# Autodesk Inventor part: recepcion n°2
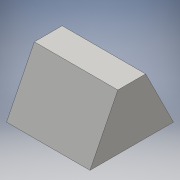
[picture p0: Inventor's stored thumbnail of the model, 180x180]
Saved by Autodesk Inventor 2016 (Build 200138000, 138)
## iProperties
Created: 2016-06
Part Number: recepcion n°2
Material: Genérico
Document SubType Name: Modeling
Designer: adm
Density: 1 g/cm^3
Appearance: Valor por defecto
Author: adm
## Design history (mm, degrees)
sketch "Boceto1"
  geometry: L1 (-60, -60)-(60, -60); L2 (60, -60)-(60, 60); L3 (60, 60)-(-60, 60); L4 (-60, 60)-(-60, -60); L5 (-60, -60)-(60, 60); L6 (60, -60)-(-60, 60); 1 further point
  constraints: 12 end point, 2 midpoint, 2 parallel, 1 horizontal, 1 perpendicular
  dimensions: "d0" = 120 distance of L3.end L2.end; "d1" = 120 distance of L2.end L1.end
node "Plano de trabajo1"
sketch "Boceto2"
  geometry: L1 (-60, -20)-(60, -20); L2 (60, -20)-(60, 20); L3 (60, 20)-(-60, 20); L4 (-60, 20)-(-60, -20); L5 (-60, -20)-(60, 20); L6 (60, -20)-(-60, 20); 1 further point
  constraints: 12 end point, 2 midpoint, 2 parallel, 1 horizontal, 1 perpendicular
  dimensions: "d3" = 120 distance of L3.end L2.end; "d4" = 40 distance of L2.end L1.end
feature "Solevación1" sketch "Boceto2" dims "d5" = 0, "d6" = 90 deg, "d7" = 0, "d8" = 90 deg
feature "Vaciado1" dims "d9" = 4
node "Sólido1"
